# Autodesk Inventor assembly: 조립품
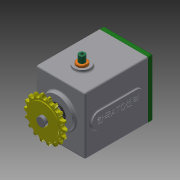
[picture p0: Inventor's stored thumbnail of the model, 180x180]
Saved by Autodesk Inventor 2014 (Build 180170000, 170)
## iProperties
Created: 2018-12
Part Number: 조립품
Document SubType Name: Assembly
Designer: kh
Mass: 2991.34 g
Surface Area: 1968.34 cm^2
Volume: 815.226 cm^3
Density: 3.66934 g/cm^3
Author: kh
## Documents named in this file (16)
- C:\Users\kh\Desktop\381207V1059\답안조립품.iam
- C:\Users\kh\Desktop\381207V1059\가변스프링.ipt
- C:\Users\kh\Desktop\381207V1059\본체.ipt
- C:\Users\kh\Desktop\381207V1059\멈춤나사 M3x8.ipt
- C:\Users\kh\Desktop\381207V1059\메인 기어 축.ipt
- C:\Users\kh\Desktop\381207V1059\베어링 608.ipt
- C:\Users\kh\Desktop\381207V1059\베어링 6003.ipt
- C:\Users\kh\Desktop\381207V1059\볼트 M4 x 10.ipt
- C:\Users\kh\Desktop\381207V1059\부시.ipt
- C:\Users\kh\Desktop\381207V1059\서브 기어 축.ipt
- C:\Users\kh\Desktop\381207V1059\스프로킷.ipt
- C:\Users\kh\Desktop\381207V1059\슬라이더.ipt
- C:\Users\kh\Desktop\381207V1059\오일 실 8 22 7.ipt
- C:\Users\kh\Desktop\381207V1059\오일 실 17 32 8.ipt
- C:\Users\kh\Desktop\381207V1059\커버.ipt
- C:\Users\kh\Desktop\381207V1059\키 5 x 5 x 18.ipt
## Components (1 placed, 1 different names)
1. 가변스프링:1
